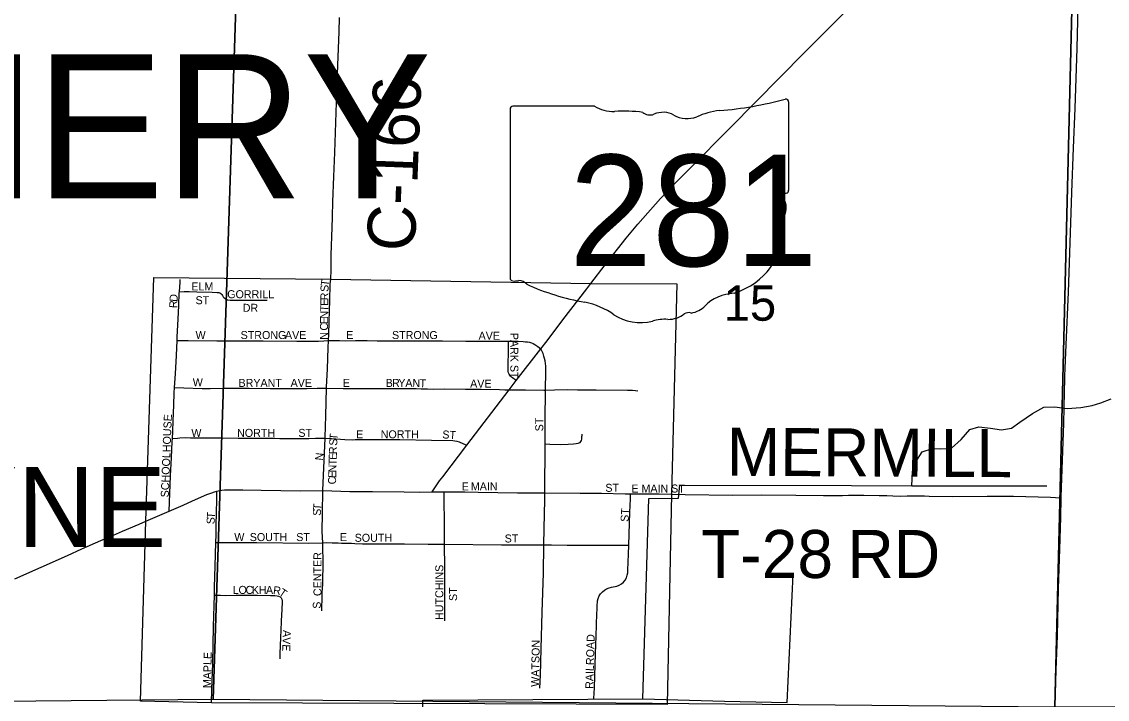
# Model space of a CAD drawing. Extents: x 1443599 to 1910620, y 1028088 to 1361369.
# Drawn here: x 1698953 to 1705737, y 1202642 to 1206877 of the extents above; entities that cross this region are included whole.
import ezdxf

# ---------------------------------------------------------------- set-up
doc = ezdxf.new("R2010")
doc.units = 0
for name, color, linetype in [('GM_X_City_Street', 7, 'Continuous'), ('GM_X_City_Street_Text', 7, 'Continuous'), ('GM_X_Corporation', 7, 'Continuous'), ('GM_X_Corporation_Text', 7, 'Continuous'), ('GM_X_County_Road', 7, 'Continuous'), ('GM_X_County_Road_Text', 7, 'Continuous'), ('GM_X_Minor_River', 7, 'Continuous'), ('GM_X_Section', 7, 'Continuous'), ('GM_X_Section_Text', 7, 'Continuous'), ('GM_X_State_Location', 7, 'Continuous'), ('GM_X_State_Route', 7, 'Continuous'), ('GM_X_State_Shield', 7, 'Continuous'), ('GM_X_Township_Road', 7, 'Continuous'), ('GM_X_Township_Road_Text', 7, 'Continuous'), ('GM_X_Township_Text', 7, 'Continuous')]:
    doc.layers.add(name, color=color, linetype=linetype)

msp = doc.modelspace()

# ---------------------------------------------------------------- linework, layer by layer
at = {"layer": 'GM_X_City_Street'}
for points in [[(1699937.9, 1205189), (1699942.4, 1205248.3), (1699943.9, 1205264.6)], [(1700870.1, 1204884.6), (1700871.4, 1204920.9), (1700874.5, 1205003.2), (1700876.7, 1205068.9), (1700878.6, 1205134.5), (1700879.2, 1205167.4), (1700879.6, 1205200.1), (1700880.4, 1205237.9), (1700883.6, 1205267.6)], [(1699923.6, 1204883.8), (1699924.6, 1204905.2), (1699929.7, 1205019.4), (1699933.6, 1205101.4), (1699937.4, 1205183.1), (1699937.9, 1205189)], [(1699937.9, 1205189), (1699967.1, 1205189.6), (1699998.9, 1205190.4), (1700046.6, 1205189), (1700142, 1205185.4), (1700173.8, 1205184.6)], [(1700173.8, 1205184.6), (1700183.7, 1205183.9), (1700190.7, 1205181.8), (1700197.1, 1205177.7), (1700203.2, 1205171.2), (1700207.7, 1205164.8), (1700212.5, 1205157.4), (1700217.7, 1205151.4), (1700224.3, 1205145.8), (1700231.6, 1205141.8), (1700239, 1205139.2), (1700255.2, 1205136.6), (1700288.3, 1205135.5), (1700388, 1205136.3), (1700471, 1205137), (1700487.5, 1205136.8)], [(1699907.8, 1204590.1), (1699913.9, 1204676.2), (1699919.3, 1204790.9), (1699923.6, 1204883.8)], [(1699923.6, 1204883.8), (1699944.4, 1204884.1), (1699992.9, 1204884.7), (1700171.2, 1204882.4), (1700236, 1204882.3), (1700462.1, 1204882.8), (1700672.4, 1204879.9), (1700764.4, 1204879.1), (1700807, 1204880.6), (1700840.8, 1204882.7), (1700870.1, 1204884.6)], [(1700858.3, 1204586.8), (1700858.4, 1204592), (1700863.5, 1204707), (1700868.4, 1204838.5), (1700870.1, 1204884.6)], [(1700870.1, 1204884.6), (1700905.4, 1204883.8), (1700937.8, 1204883.1), (1700979.2, 1204883), (1701038.3, 1204883.9), (1701089.6, 1204883.9), (1701110.8, 1204883.9), (1701173.8, 1204882.6), (1701271.3, 1204881.2), (1701353.3, 1204882.5), (1701418.5, 1204882.4), (1701581.8, 1204881.9), (1701728.7, 1204879.9), (1701908.2, 1204879.5), (1701940.9, 1204879.6), (1701995.3, 1204879.4)], [(1702043.6, 1204633.7), (1702019.1, 1204651.6), (1702013, 1204655.8), (1702007.4, 1204661.1), (1702002.7, 1204666.7), (1701998.2, 1204674.6), (1701995.3, 1204682.7), (1701993.6, 1204690.4), (1701992.1, 1204706.9), (1701992.6, 1204740.4), (1701995, 1204807.9), (1701995.3, 1204824.9), (1701995, 1204840.9), (1701995.1, 1204858.2), (1701995.3, 1204879.4)], [(1701995.3, 1204879.4), (1702054.6, 1204879.2), (1702086.8, 1204877.4), (1702101, 1204876.6), (1702113.6, 1204875.3), (1702125.2, 1204873), (1702139.2, 1204869), (1702149.1, 1204865), (1702159, 1204859.6), (1702166.6, 1204855.1), (1702178.3, 1204847), (1702197.4, 1204833)], [(1702226.1, 1204574.5), (1702226.4, 1204591.6), (1702228.5, 1204673.8), (1702227.2, 1204723.3), (1702223.4, 1204756.1), (1702220.2, 1204772.3), (1702216.6, 1204786.7), (1702211.9, 1204802.4), (1702197.4, 1204833)], [(1699894.1, 1204271.2), (1699896.3, 1204316), (1699898.7, 1204381.3), (1699902.3, 1204479.6), (1699905.4, 1204556.8), (1699907.8, 1204590.1)], [(1699907.8, 1204590.1), (1699966.4, 1204588.2), (1700080.8, 1204584.7), (1700129.8, 1204584.5), (1700211.6, 1204585.3), (1700309.7, 1204585.8), (1700375.1, 1204585.8), (1700505.9, 1204584.8), (1700669.1, 1204584), (1700734.6, 1204584.6), (1700800, 1204585.9), (1700832.6, 1204586.4), (1700858.3, 1204586.8)], [(1700848.1, 1204273.6), (1700848.4, 1204280.8), (1700853.2, 1204412.3), (1700858.3, 1204586.8)], [(1700858.3, 1204586.8), (1700960.9, 1204584.6), (1701074.9, 1204583.6), (1701238.7, 1204583.3), (1701290, 1204584.5), (1701336.8, 1204584.7), (1701384.1, 1204584.3), (1701418.3, 1204583.3), (1701448.2, 1204582.5), (1701487.7, 1204581.4), (1701529.2, 1204580.3), (1701594.4, 1204581.7), (1701725.3, 1204580.7), (1701823.4, 1204579.9), (1701937.9, 1204577.8), (1701971.1, 1204576.1), (1701999, 1204575.7)], [(1701999, 1204575.7), (1702101.3, 1204575.6), (1702215.9, 1204574.4), (1702226.1, 1204574.5)], [(1702223.5, 1204237.4), (1702223.6, 1204251.5), (1702223.1, 1204383.2), (1702226.1, 1204574.5)], [(1702226.1, 1204574.5), (1702281.3, 1204575.6), (1702363.7, 1204577.9), (1702425.5, 1204576.8), (1702542.3, 1204575.9), (1702738.7, 1204574.6), (1702770.8, 1204574.1), (1702787.6, 1204571.7), (1702803.6, 1204568.9)], [(1702223.5, 1204237.4), (1702253.8, 1204236.5), (1702319, 1204234.7), (1702368, 1204235.5), (1702400.5, 1204238), (1702416.8, 1204239.9), (1702429.9, 1204242.2), (1702436.8, 1204244.1), (1702441.8, 1204246.9), (1702446.1, 1204252.3), (1702450.3, 1204260.1), (1702452.3, 1204267.1), (1702453.2, 1204274.3), (1702454.1, 1204283.3), (1702454.7, 1204289.7), (1702454.5, 1204299.5)], [(1699875.2, 1203818.2), (1699877, 1203873.6), (1699882.3, 1204037.4), (1699888.1, 1204152.2), (1699893.2, 1204250.5), (1699894.1, 1204271.2)], [(1699894.1, 1204271.2), (1699925.7, 1204274.4), (1699941.8, 1204276), (1699974.4, 1204276.8), (1700007.4, 1204276.3), (1700040.4, 1204275.2), (1700205.9, 1204275.8), (1700305, 1204274.4), (1700339.3, 1204273.9), (1700403.2, 1204272.9), (1700468.8, 1204273.1), (1700533.8, 1204272.8), (1700566.6, 1204271.8), (1700614.3, 1204271.4), (1700661.7, 1204271.8), (1700708, 1204272.2), (1700747.3, 1204272.6), (1700788.3, 1204273), (1700848.1, 1204273.6)], [(1700834.1, 1203945.6), (1700848.1, 1204273.6)], [(1700848.1, 1204273.6), (1700889.6, 1204270.9), (1700972.3, 1204265.6), (1701021.4, 1204264), (1701037.2, 1204264.7), (1701184.3, 1204264.8), (1701316.3, 1204264.8), (1701514.5, 1204261.9), (1701646.4, 1204258.5), (1701672.3, 1204254.6), (1701687.1, 1204250.5), (1701709.5, 1204240.5), (1701734.3, 1204229.4)], [(1702221.5, 1203931.5), (1702223.5, 1204237.4)], [(1700165.9, 1203622.5), (1700167, 1203670.5), (1700168.8, 1203748.3), (1700169.8, 1203788.1), (1700170.8, 1203832.2), (1700171.6, 1203865.3), (1700172.4, 1203899.1), (1700172.5, 1203915.7), (1700172.7, 1203942.8)], [(1700833.9, 1203619.9), (1700830.5, 1203689.3), (1700831.7, 1203805), (1700834.1, 1203945.6)], [(1701517.4, 1203938.3), (1701543, 1203938.3), (1701568.9, 1203938.4), (1701592.3, 1203938.4)], [(1701595.3, 1203610.3), (1701595.6, 1203743.1), (1701593.3, 1203891.9), (1701592.9, 1203908.4), (1701592.3, 1203938.4)], [(1701592.3, 1203938.4), (1701607.6, 1203938.4), (1701722.5, 1203937.7), (1701804.7, 1203935.3), (1702051, 1203932.4), (1702182, 1203931.9), (1702221.5, 1203931.5)], [(1702216.4, 1203607.1), (1702218, 1203708.6), (1702221.8, 1203888.2), (1702221.7, 1203904.6), (1702221.5, 1203931.5)], [(1702221.5, 1203931.5), (1702443.2, 1203928.9), (1702575.2, 1203928.9), (1702723.5, 1203926.5), (1702758.3, 1203926.5)], [(1702746.2, 1203605.4), (1702752.9, 1203811.3), (1702756.8, 1203893.5), (1702758.3, 1203926.5)], [(1702758.3, 1203926.5), (1702844.8, 1203926.3), (1702937, 1203924.8), (1703014.4, 1203923.7)], [(1700156.8, 1203293.1), (1700158.3, 1203342.4), (1700162.4, 1203473.6), (1700165.9, 1203622.5)], [(1700165.9, 1203622.5), (1700191.3, 1203622.3), (1700260.8, 1203621.6), (1700421.8, 1203621.7), (1700745.8, 1203618.2), (1700833.9, 1203619.9)], [(1700827.9, 1203193.4), (1700827.5, 1203226.1), (1700829.6, 1203259.2), (1700831, 1203308.5), (1700834.4, 1203358.2), (1700835.8, 1203507.6), (1700835.4, 1203590.8), (1700833.9, 1203619.9)], [(1700833.9, 1203619.9), (1700859.3, 1203620.6), (1700893.8, 1203619.7), (1700913.1, 1203619.2), (1700930.1, 1203618.7), (1700950.5, 1203618.2), (1700975.7, 1203617.5), (1701013.7, 1203616.5), (1701034.1, 1203616), (1701083.2, 1203614), (1701132.3, 1203612.5), (1701230.5, 1203613.4), (1701345, 1203613.1), (1701492.6, 1203610.9), (1701595.3, 1203610.3)], [(1701597.4, 1203131.8), (1701596.9, 1203264), (1701597.9, 1203412.9), (1701597.1, 1203495.5), (1701595.3, 1203578), (1701595.3, 1203610.3)], [(1701595.3, 1203610.3), (1701952.1, 1203608), (1702099.9, 1203607.9), (1702182, 1203607.4), (1702216.4, 1203607.1)], [(1702190.7, 1202711.6), (1702195.2, 1202793.3), (1702199.7, 1202956.7), (1702205.5, 1203185.6), (1702213.6, 1203430.7), (1702216.4, 1203607.1)], [(1702216.4, 1203607.1), (1702263.7, 1203606.6), (1702361, 1203605.5), (1702377.2, 1203605.4), (1702393.5, 1203605.3), (1702474.9, 1203605.1), (1702540.4, 1203605.1), (1702688.2, 1203605.3), (1702746.2, 1203605.4)], [(1702528.6, 1202647.2), (1702531.4, 1202713), (1702535.6, 1202858.8), (1702539.8, 1202986.5), (1702542.4, 1203031.1), (1702543.2, 1203055), (1702544.2, 1203088.3), (1702545.5, 1203127), (1702546.5, 1203157.3), (1702549.2, 1203223.2), (1702551.8, 1203256), (1702555.3, 1203272.1), (1702561.2, 1203287.5), (1702570, 1203301.3), (1702581.5, 1203313), (1702594.4, 1203323.3), (1702608.2, 1203332.1), (1702623.3, 1203338.5), (1702639.2, 1203342.4), (1702671.7, 1203348.7), (1702687.1, 1203354.4), (1702701.2, 1203362.7), (1702713.5, 1203373.6), (1702723.6, 1203386.5), (1702731.3, 1203401), (1702736.6, 1203416.6), (1702739.7, 1203432.7), (1702741.2, 1203449.2), (1702744.3, 1203548), (1702746.2, 1203605.4)], [(1700139.7, 1202619.9), (1700140.9, 1202702.9), (1700147.6, 1202867), (1700151, 1203096.4), (1700156.8, 1203293.1)], [(1700156.8, 1203293.1), (1700194.1, 1203292), (1700226.6, 1203291), (1700292.3, 1203291.8), (1700424.3, 1203291.7), (1700507.1, 1203289.9), (1700534.6, 1203289.4), (1700549.4, 1203288.1), (1700557.9, 1203285.9), (1700567.1, 1203281.6), (1700573.8, 1203275.4), (1700578.3, 1203266.5), (1700580.8, 1203257.8), (1700581.4, 1203249.6), (1700580.1, 1203235.3), (1700579.2, 1203216.7), (1700577.9, 1203197.3), (1700576.8, 1203174.4), (1700573.7, 1203125.1), (1700569.1, 1203025.9), (1700565.5, 1202926.9), (1700565.8, 1202894.8)]]:
    msp.add_lwpolyline(points, dxfattribs=at)
at = {"layer": 'GM_X_Corporation'}
msp.add_lwpolyline([(1699694.7, 1202630.5), (1699727.3, 1203754.5), (1699777.6, 1205278.2), (1700883.6, 1205267.6), (1702509.5, 1205241.1), (1703046.2, 1205239.1), (1703014.4, 1203923.7), (1702986.9, 1202608.3), (1700139.7, 1202619.9)], close=True, dxfattribs=at)
at = {"layer": 'GM_X_County_Road'}
msp.add_lwpolyline([(1700883.6, 1205267.6), (1700886.9, 1205325.8), (1700886.9, 1205357.6), (1700886.6, 1205391.7), (1700886.3, 1205423.5), (1700888, 1205470.9), (1700890.4, 1205538.8), (1700892.2, 1205587.2), (1700894.7, 1205658.5), (1700898, 1205750.6), (1700903.6, 1205908.9), (1700908.9, 1206058.2), (1700915.7, 1206247.1), (1700920.1, 1206371.2), (1700924.6, 1206496.3), (1700930.3, 1206657.7), (1700935.8, 1206812.4), (1700939.1, 1206903.7)], dxfattribs=at)
at = {"layer": 'GM_X_Minor_River'}
for points in [[(1704515.3, 1203976.5), (1704520.6, 1204064.6), (1704539.7, 1204126.5), (1704580.7, 1204188), (1704645.2, 1204209), (1704695.3, 1204206.2), (1704763.6, 1204211.2), (1704824.6, 1204264.4), (1704877.7, 1204327.7), (1704934.1, 1204344.9), (1705006.2, 1204335.7), (1705076.2, 1204326.6), (1705138.5, 1204335.6), (1705191.3, 1204372.9), (1705270.3, 1204427.8), (1705341.1, 1204466.8), (1705407.4, 1204469.8), (1705485.4, 1204458.5), (1705571.7, 1204465.2), (1705642.1, 1204478.1), (1705696.5, 1204495.3), (1705761.1, 1204520.4)], [(1702833.9, 1202643.5), (1702871.6, 1203895.9), (1703058.1, 1203899), (1703065.4, 1203979.1), (1704138.3, 1203978.4), (1704515.3, 1203976.5), (1705359.5, 1203975.3)], [(1700138.5, 1201356.3), (1700174, 1201822.9), (1700186.7, 1201995.1), (1700226.6, 1202106.8), (1700291.8, 1202177.9), (1700389.1, 1202244.6), (1700509.9, 1202268.8), (1700654.3, 1202272.5), (1701358.8, 1202311.7), (1701400.9, 1202313), (1701443.2, 1202326.4), (1701461.9, 1202368.2), (1701460.1, 1202636.9), (1702833.9, 1202643.5), (1703345.1, 1202629.5), (1703736, 1202621.4), (1703774.6, 1203420.7)]]:
    msp.add_lwpolyline(points, dxfattribs=at)
at = {"layer": 'GM_X_Section'}
for points in [[(1695009.7, 1207930.9), (1700321.8, 1207924.1), (1700149.2, 1202639.6), (1694826.5, 1202590.6)], [(1700321.8, 1207924.1), (1705537.7, 1207892.2), (1705408.9, 1202593.2), (1700149.2, 1202639.6)], [(1705537.7, 1207892.2), (1710813.9, 1207877.7), (1710715.3, 1202600.3), (1705408.9, 1202593.2)]]:
    msp.add_lwpolyline(points, close=True, dxfattribs=at)
at = {"layer": 'GM_X_State_Route'}
for points in [[(1703125.6, 1205957.2), (1703381.2, 1206216.1), (1703693, 1206530.5), (1703842.9, 1206682.3), (1703947.2, 1206786.7), (1704108.8, 1206949.8), (1704235.1, 1207078.8), (1704385.3, 1207230), (1704467.1, 1207312.3)], [(1702509.5, 1205241.1), (1702598.1, 1205356.3), (1702730.8, 1205523.1), (1702804.1, 1205611.3), (1702945.3, 1205770.8), (1703024, 1205854.3), (1703125.6, 1205957.2)], [(1702485.1, 1205207.6), (1702497.2, 1205224.2), (1702509.5, 1205241.1)], [(1701584.1, 1204032.9), (1701734.3, 1204229.4), (1701999, 1204575.7), (1702024, 1204608.3), (1702043.6, 1204633.7), (1702197.4, 1204833), (1702235.5, 1204882.4), (1702335.1, 1205013.7), (1702485.1, 1205207.6)], [(1699727.3, 1203754.5), (1699815.1, 1203792), (1699875.2, 1203818.2), (1699903.3, 1203830.4), (1699961.4, 1203855.5), (1700019.9, 1203882.1), (1700110, 1203920.9), (1700140.6, 1203932.9), (1700157.4, 1203938.5), (1700172.1, 1203942.6), (1700172.7, 1203942.8), (1700188.1, 1203946.3), (1700204.3, 1203949.1), (1700220.8, 1203950.6), (1700253.3, 1203951.4), (1700285.8, 1203951.5), (1700334.7, 1203950.7), (1700449.2, 1203948.3), (1700694.8, 1203943.9), (1700834.1, 1203945.6), (1701003.4, 1203941), (1701144.5, 1203939.5), (1701343.2, 1203937.3), (1701440.1, 1203935.2), (1701517.4, 1203938.3), (1701563.6, 1204006.1), (1701584.1, 1204032.9)], [(1698910.2, 1203393.8), (1699239.5, 1203541.2), (1699328.9, 1203581), (1699447.4, 1203633.1), (1699506.8, 1203658.6), (1699581.8, 1203691.5), (1699686.8, 1203736.7), (1699727.3, 1203754.5)]]:
    msp.add_lwpolyline(points, dxfattribs=at)
at = {"layer": 'GM_X_State_Shield'}
for p, q in [((1702005.6, 1206331), (1702005.6, 1205274.3)), ((1702532.4, 1206349.2), (1702022.7, 1206349.2)), ((1703745.8, 1205822.6), (1703745.8, 1206375.4)), ((1703745.6, 1205822.7), (1703745.8, 1205822.6))]:
    msp.add_line(p, q, dxfattribs=at)
for centre, major_axis, start_param, end_param in [((1703125.9, 1207789.7), (1845.5, 0), 4.814394, 5.042369), ((1703726.5, 1206377.6), (19.4, 0), 6.141152, 7.989035), ((1702025.5, 1206333.2), (20.2, 0), 1.712693, 3.28349), ((1702653.7, 1206471.8), (195.5, 0), 4.042523, 4.731795), ((1702718.6, 1205756), (702, 0), 1.404758, 1.657858), ((1702877.9, 1206338.7), (56.4, 0), 3.836095, 5.185415), ((1702960.7, 1206216.6), (117.3, 0), 0.950623, 2.079405), ((1703112.1, 1206384.1), (141.1, 0), 4.081561, 5.145723), ((1703361.3, 1206026.4), (371.3, 0), 1.699011, 2.107814), ((1703741.3, 1205782), (30, 0), 1.883978, 3.671073), ((1703725.1, 1205820.5), (20.7, 0), 5.05454, 6.418171), ((1703550.6, 1205712.2), (180, 0), 5.934695, 6.695948), ((1703815.2, 1205591.3), (130.9, 0), 2.387724, 3.262537), ((1703229.3, 1205521), (461.6, 0), 5.101752, 6.440018), ((1702025.7, 1205272), (20.3, 0), 3.00124, 4.508301), ((1702028.8, 1205380.1), (155.2, 0), 4.665946, 4.897461), ((1702060.6, 1205213.4), (56, 0), 0.519207, 1.627899), ((1702767.2, 1206162.7), (1332.7, 0), 4.195997, 4.488961), ((1703423.9, 1204977.7), (252.8, 0), 1.647645, 2.488434), ((1702369.8, 1204799.7), (417, 0), 0.823519, 1.323587), ((1702820.8, 1205208.1), (264.6, 0), 4.026481, 4.996735), ((1702993, 1205129), (141, 0), 4.691044, 5.507374), ((1703120.6, 1205026.7), (39.7, 0), 1.147584, 2.315152), ((1703103.6, 1205171.9), (149.1, 0), 4.937069, 5.64225), ((1702973.7, 1204842.8), (217.4, 0), 1.495662, 1.94098)]:
    msp.add_ellipse(centre, major_axis=major_axis, ratio=0.8, start_param=start_param, end_param=end_param, dxfattribs=at)
at = {"layer": 'GM_X_Township_Road'}
for points in [[(1705449.4, 1203900.2), (1705449.6, 1203908), (1705453, 1204022.6), (1705460.4, 1204251.6), (1705465.3, 1204366.2), (1705467.9, 1204464.7), (1705468.8, 1204563.1), (1705472, 1204645.1), (1705471.7, 1204661.5), (1705473.1, 1204710.5), (1705479.2, 1204857.9), (1705493.8, 1205185.5), (1705502.7, 1205431.5), (1705516.1, 1205808.9), (1705526.7, 1206087.7), (1705535.7, 1206334.1), (1705548, 1206710.9), (1705558, 1207054.6), (1705568, 1207399.3), (1705581.3, 1207891.8), (1705581.7, 1207906.1)], [(1703014.4, 1203923.7), (1703099.6, 1203920.7), (1703395.8, 1203918), (1703577, 1203920.2), (1703791.1, 1203918), (1703962.8, 1203916.3), (1704021.8, 1203915.6), (1704083.1, 1203916.2), (1704119.1, 1203916.5), (1704156.2, 1203916.9), (1704215, 1203916.6), (1704311.1, 1203916.3), (1704359.2, 1203914.7), (1704396.8, 1203913.4), (1704442.8, 1203911.9), (1704485.8, 1203912.2), (1704528.7, 1203912.5), (1704568.4, 1203912.7), (1704594.9, 1203912.3), (1704624.2, 1203911.8), (1704772.2, 1203909.2), (1704986.2, 1203911), (1705150.9, 1203910.3), (1705381.3, 1203904.6), (1705414.3, 1203902.5), (1705449.4, 1203900.2)], [(1705408.9, 1202572.7), (1705410.8, 1202624.4), (1705412.8, 1202677.9), (1705418, 1202825.5), (1705424.8, 1203038.7), (1705432.5, 1203334), (1705440.6, 1203580), (1705446, 1203776.9), (1705449.4, 1203900.2)]]:
    msp.add_lwpolyline(points, dxfattribs=at)

# ---------------------------------------------------------------- texts
at = {"layer": 'GM_X_City_Street_Text'}
for s, rotation, p in [('ELM', 0.00001, (1700012.7, 1205196.8)), ('T', 81.93945, (1700870.2, 1205221.1)), ('D', 86.52317, (1699925.8, 1205124.9)), ('GORRILL', 0.00001, (1700237.1, 1205148.4)), ('R', 89.23386, (1700869, 1205134.8)), ('S', 88.96184, (1700869.7, 1205187.5)), ('R', 87.59483, (1699924.1, 1205085.6)), ('ST', 0.00001, (1700039.1, 1205110.8)), ('DR', 0.00001, (1700333.9, 1205063.3)), ('T', 89.22963, (1700868.1, 1205064.4)), ('E', 89.22963, (1700868.5, 1205099.6)), ('N', 89.22701, (1700867.5, 1205020.4)), ('C', 89.21014, (1700866.5, 1204945.6)), ('E', 89.22963, (1700867, 1204985.2)), ('W', 0.00001, (1700039.1, 1204893.2)), ('STRONG', 0.00001, (1700320.7, 1204893.2)), ('AVE', 0.00001, (1700597.9, 1204893.2)), ('N', 89.23492, (1700865.7, 1204888.4)), ('E', 0.00001, (1700980.7, 1204893.2)), ('STRONG', 0.00001, (1701266.7, 1204893.2)), ('AVE', 0.00001, (1701807.9, 1204888.8)), ('PARK ST', 270, (1702006.5, 1204932.2)), ('W', 0.00001, (1700021.5, 1204598.4)), ('BRYANT', 0.00001, (1700307.5, 1204594)), ('AVE', 0.00001, (1700633.1, 1204594)), ('E', 0.00001, (1700958.7, 1204594)), ('B', 359.87856, (1701227.1, 1204594)), ('R', 359.89911, (1701266.7, 1204593.9)), ('Y', 359.8907, (1701306.3, 1204593.8)), ('A', 359.86884, (1701350.3, 1204593.7)), ('N', 358.47015, (1701394, 1204593.6)), ('T', 357.13078, (1701437.7, 1204592.5)), ('AVE', 0.00001, (1701755.1, 1204589.6)), ('SCHOOLHOUSE', 87.77492, (1699871.3, 1203902.9)), ('ST', 90, (1702212.1, 1204316.2)), ('W', 0.00001, (1700012.7, 1204281.6)), ('NORTH', 0.00001, (1700298.7, 1204281.6)), ('ST', 0.00001, (1700681.5, 1204281.6)), ('T', 85.21366, (1700925.3, 1204260.2)), ('E', 0.00001, (1701042.3, 1204272.8)), ('NORTH', 0.00001, (1701196.3, 1204272.8)), ('ST', 356.18786, (1701579.8, 1204272.8)), ('S', 87.51281, (1700923.8, 1204225.6)), ('N', 84.29372, (1700835, 1204132.3)), ('E', 88.28428, (1700921.1, 1204137.8)), ('R', 88.20249, (1700922.2, 1204173)), ('N', 88.28136, (1700918.7, 1204058.6)), ('T', 88.27836, (1700920.1, 1204102.6)), ('C', 88.2996, (1700916.5, 1203983.9)), ('E', 88.27836, (1700917.7, 1204023.5)), ('E', 0.00001, (1701702.3, 1203947.2)), ('MAIN', 0.00001, (1701759.5, 1203947.2)), ('ST', 0.00001, (1702599.9, 1203938.4)), ('E MAIN ST', 0.00001, (1702762.7, 1203934)), ('S', 87.62201, (1700821.7, 1203787.6)), ('T', 85.8988, (1700823.2, 1203822.4)), ('ST', 86.41175, (1702744.5, 1203749.2)), ('S', 87.15804, (1700157.3, 1203734.7)), ('T', 85.81707, (1700159, 1203769.6)), ('W', 0.00001, (1700281.1, 1203630.4)), ('SOUTH', 0.00001, (1700377.9, 1203630.4)), ('ST', 0.00001, (1700668.3, 1203630.4)), ('E', 0.00001, (1700941.1, 1203630.4)), ('SOUTH', 0.00001, (1701033.5, 1203626)), ('ST', 0.00001, (1701970.7, 1203621.6)), ('CENTER', 90, (1700826.1, 1203286.6)), ('HUTCHINS', 90, (1701587.3, 1203137)), ('L', 359.89071, (1700272.3, 1203300.4)), ('O', 359.90283, (1700307.5, 1203300.3)), ('C', 359.89911, (1700351.5, 1203300.2)), ('K', 359.8907, (1700391.1, 1203300.2)), ('H', 359.90283, (1700435.1, 1203300.1)), ('A', 359.8907, (1700479.1, 1203300)), ('R', 352.15498, (1700521.3, 1203300.1)), ('T', 326.1963, (1700555, 1203296.8)), ('ST', 90, (1701673.4, 1203255.8)), ('S', 90, (1700821.7, 1203207.4)), ('AVE', 268.02609, (1700585.3, 1203075.1)), ('WATSON', 89.02953, (1702185.7, 1202719.1)), ('RAILROAD', 88.40666, (1702524.5, 1202706)), ('MAPLE', 88.77814, (1700135.3, 1202710.5))]:
    msp.add_text(s, height=50, rotation=rotation, dxfattribs=at).set_placement(p)
at = {"layer": 'GM_X_Corporation_Text'}
msp.add_text('WAYNE', height=500, rotation=0.00001, dxfattribs=at).set_placement((1697403.5, 1203592.9))
at = {"layer": 'GM_X_County_Road_Text'}
msp.add_text('C-166', height=300, rotation=87.84533, dxfattribs=at).set_placement((1701409.3, 1205438.1))
at = {"layer": 'GM_X_Section_Text'}
msp.add_text('15', height=221, rotation=0.00001, dxfattribs=at).set_placement((1703339.1, 1205007.8))
at = {"layer": 'GM_X_State_Location'}
for s in ['s', 'r']:
    msp.add_text(s, height=1, dxfattribs=at).set_placement((1702856.1, 1205732.4))
msp.add_text('281', height=1, rotation=0.00001, dxfattribs=at).set_placement((1702503.1, 1205659.7))
at = {"layer": 'GM_X_State_Shield'}
msp.add_text('281', height=696.1, dxfattribs=at).set_placement((1702373.9, 1205348.9))
at = {"layer": 'GM_X_Township_Road_Text'}
for s, rotation, p in [('MERMILL', 359.70243, (1703358, 1204038.9)), ('T-28', 0.00001, (1703198.3, 1203399.5)), ('RD', 0.00001, (1704113.5, 1203400.1))]:
    msp.add_text(s, height=300, rotation=rotation, dxfattribs=at).set_placement(p)
at = {"layer": 'GM_X_Township_Text'}
msp.add_text('MONTGOMERY', height=900, rotation=0.00001, dxfattribs=at).set_placement((1692622.2, 1205773.2))

doc.saveas('drawing.dxf')
